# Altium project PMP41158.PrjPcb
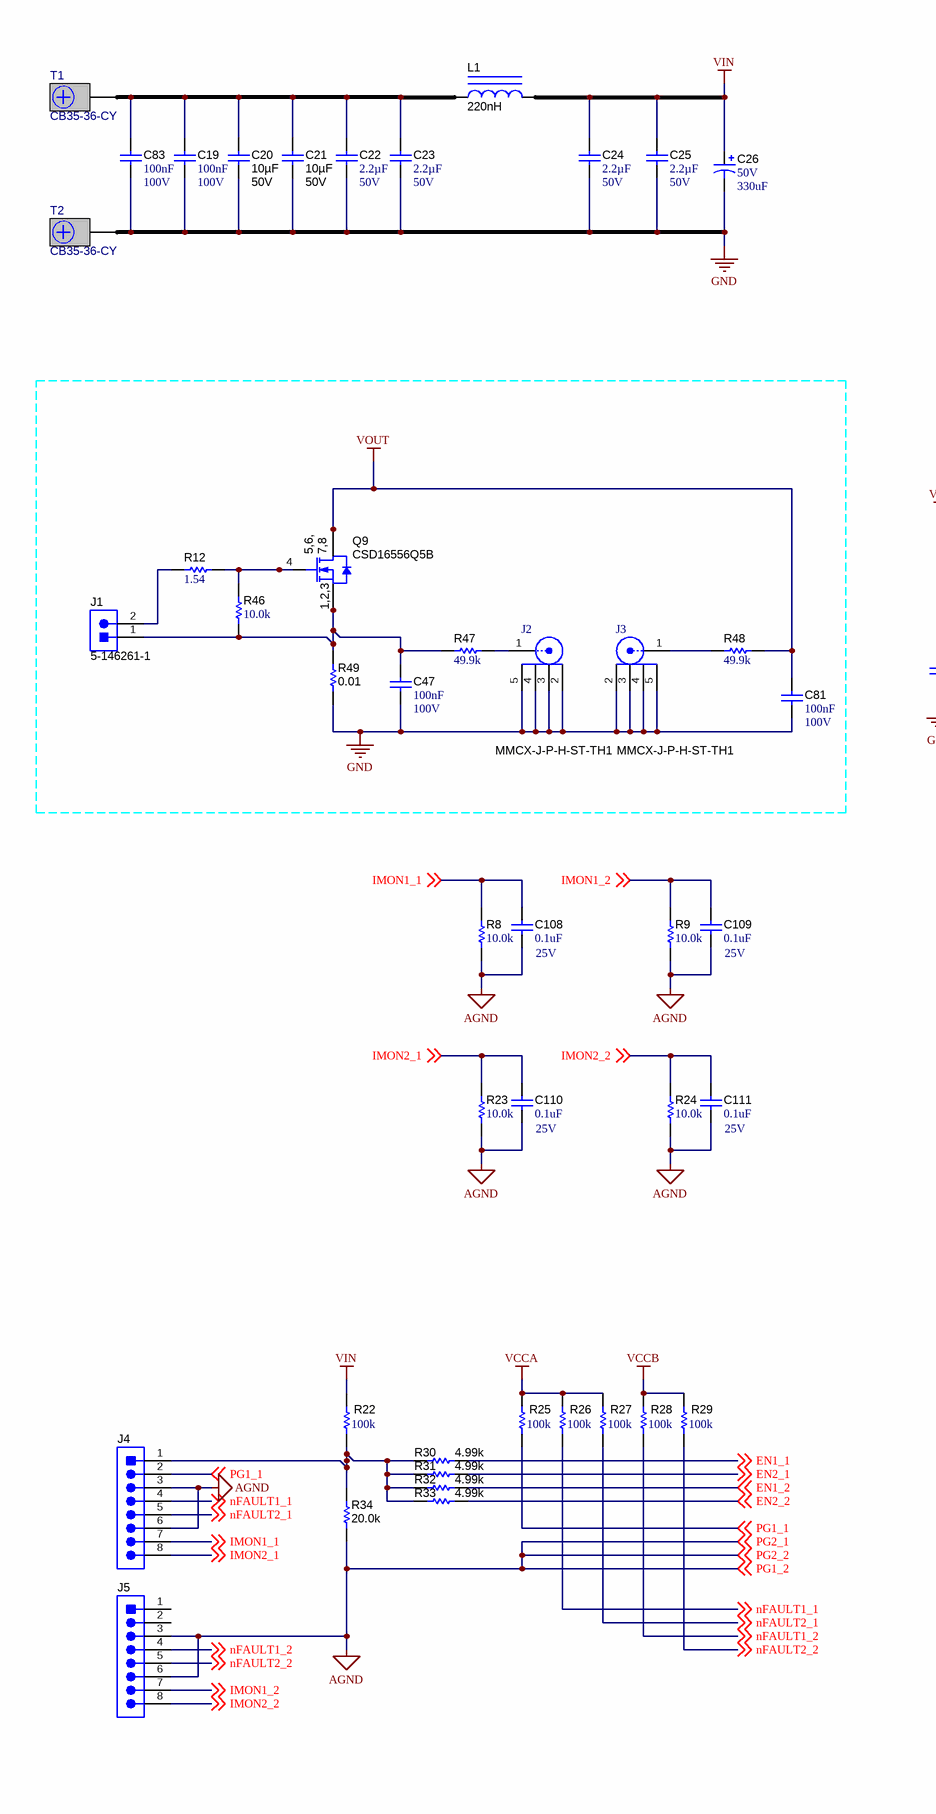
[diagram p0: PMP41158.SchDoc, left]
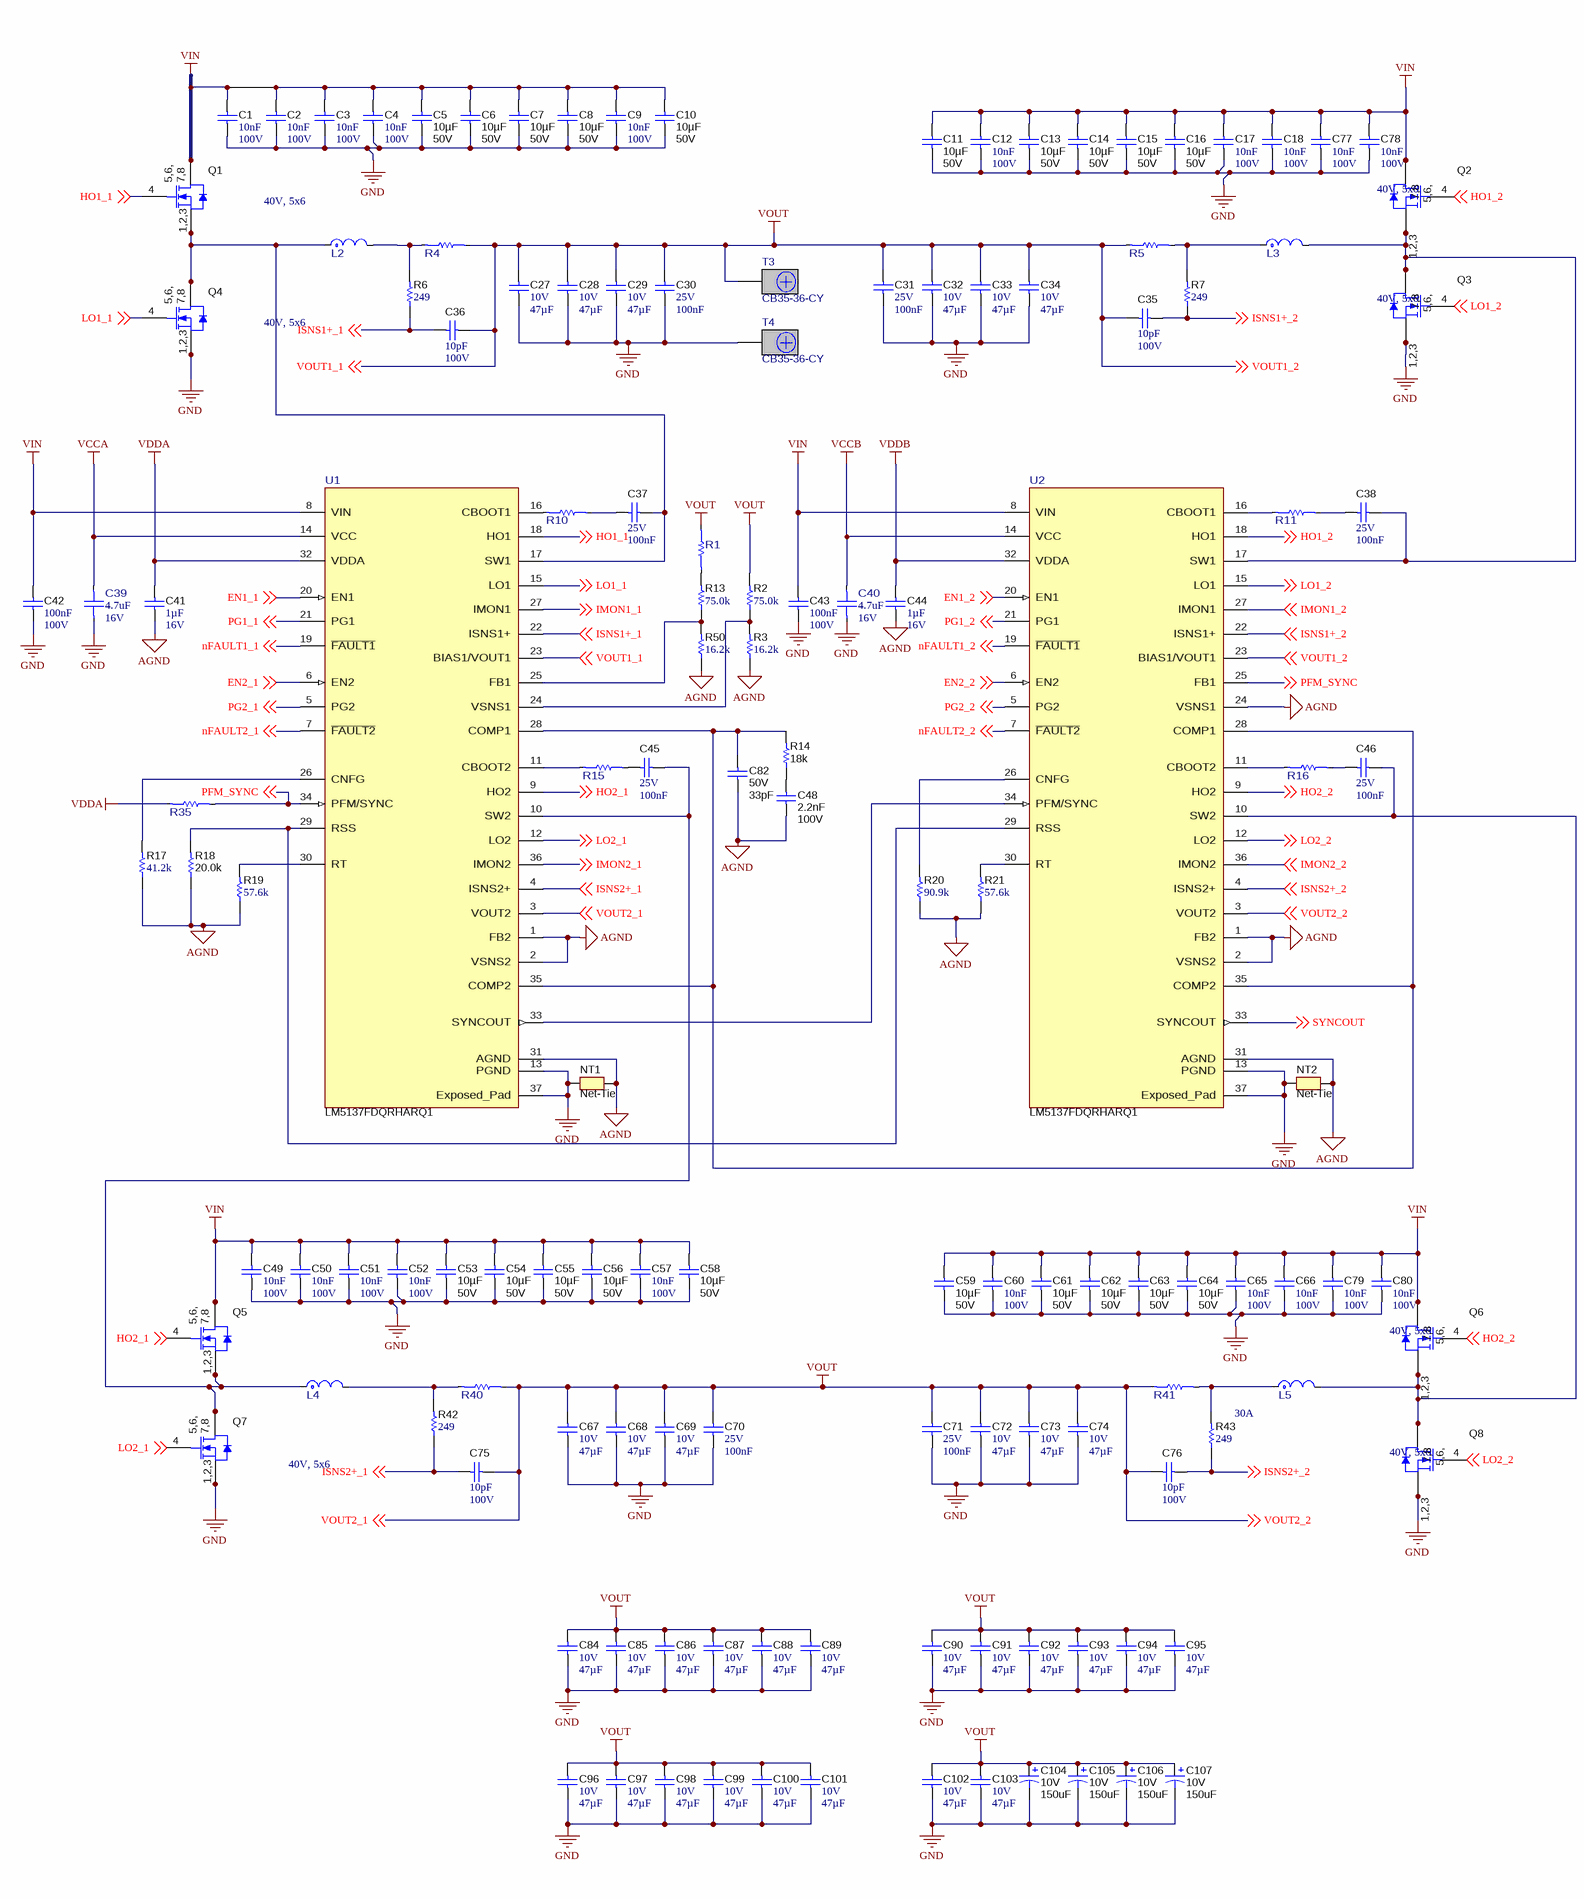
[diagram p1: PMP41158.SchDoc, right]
CopyrightYear: 2025; PCB_Layout: Shelly Xie; PCB_Rev: A; PRJ_Customer: Public Release; PRJ_Engineer: Shelly Xie; PRJ_Number: PMP41158; PRJ_Title: PMP41158; SCH_Rev: A; TechSupport: http://www.ti.com/support; TID: N/A
2 sheets, 203 parts. Net scope: global (net labels, ports and power ports of the same name join across sheets).
Board file: PMP41158-Finial.PcbDoc
Sheets:
  PMP41158.SchDoc
  PMP41158_Hardware.SchDoc

## Sheet PMP41158.SchDoc
size 558 x 431 mm; Date: Not shown in title block; ApprovedBy: Not shown in title block; CheckedBy: Not shown in title block; Author: Not shown in title block; CompanyName: Not shown in title block; Engineer: Not shown in title block; Organization: Not shown in title block; Address1: Not shown in title block; Address2: Not shown in title block; Address3: Not shown in title block; Address4: Not shown in title block; DocumentNumber: 2; Revision: Use project parameter SCH_Rev; SheetNumber: 1; SheetTotal: 2; PageSetup: Record=PageOptions¦CenterHorizontal=True¦CenterVertical=True¦PrintScale=1.00¦XCorrection=1.00¦YCorrection=1.00¦PrintKind=0¦BorderSize=5000000¦LeftOffset=0¦BottomOffset=0¦Orientation=2¦PaperLength=1000¦PaperWidth=1000¦Scale=100¦PaperSource=15¦PrintQuality=600¦MediaType=1¦DitherType=10¦PaperKind=Letter¦PrintScaleMode=1

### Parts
C1  Cap_F: 10nF  VDC_V: 100V  [0603]  (hidden comment: CGA3E2X7R2A103K080AA)
C2  Cap_F: 10nF  VDC_V: 100V  [0603]  (hidden comment: CGA3E2X7R2A103K080AA)
C3  Cap_F: 10nF  VDC_V: 100V  [0603]  (hidden comment: CGA3E2X7R2A103K080AA)
C4  Cap_F: 10nF  VDC_V: 100V  [0603]  (hidden comment: CGA3E2X7R2A103K080AA)
C5  ValueDisplayed: 10µF  VDC_V: 50V  [1210_280]  (hidden comment: CGA6P3X7S1H106K250AE)
C6  ValueDisplayed: 10µF  VDC_V: 50V  [1210_280]  (hidden comment: CGA6P3X7S1H106K250AE)
C7  ValueDisplayed: 10µF  VDC_V: 50V  [1210_280]  (hidden comment: CGA6P3X7S1H106K250AE)
C8  ValueDisplayed: 10µF  VDC_V: 50V  [1210_280]  (hidden comment: CGA6P3X7S1H106K250AE)
C9  Cap_F: 10nF  VDC_V: 100V  [0603]  (hidden comment: CGA3E2X7R2A103K080AA)
C10  ValueDisplayed: 10µF  VDC_V: 50V  [1210_280]  (hidden comment: CGA6P3X7S1H106K250AE)
C11  ValueDisplayed: 10µF  VDC_V: 50V  [1210_280]  (hidden comment: CGA6P3X7S1H106K250AE)
C12  Cap_F: 10nF  VDC_V: 100V  [0603]  (hidden comment: CGA3E2X7R2A103K080AA)
C13  ValueDisplayed: 10µF  VDC_V: 50V  [1210_280]  (hidden comment: CGA6P3X7S1H106K250AE)
C14  ValueDisplayed: 10µF  VDC_V: 50V  [1210_280]  (hidden comment: CGA6P3X7S1H106K250AE)
C15  ValueDisplayed: 10µF  VDC_V: 50V  [1210_280]  (hidden comment: CGA6P3X7S1H106K250AE)
C16  ValueDisplayed: 10µF  VDC_V: 50V  [1210_280]  (hidden comment: CGA6P3X7S1H106K250AE)
C17  Cap_F: 10nF  VDC_V: 100V  [0603]  (hidden comment: CGA3E2X7R2A103K080AA)
C18  Cap_F: 10nF  VDC_V: 100V  [0603]  (hidden comment: CGA3E2X7R2A103K080AA)
C19  Cap_F: 100nF  VDC_V: 100V  [0805_HV]  (hidden comment: GCM21BR72A104KA37L)
C20  ValueDisplayed: 10µF  VDC_V: 50V  [1210_280]  (hidden comment: CGA6P3X7S1H106K250AE)
C21  ValueDisplayed: 10µF  VDC_V: 50V  [1210_280]  (hidden comment: CGA6P3X7S1H106K250AE)
C22  Cap_F: 2.2µF  VDC_V: 50V  [0805L]  (hidden comment: CGA4J3X7R1H225K125AE)
C23  Cap_F: 2.2µF  VDC_V: 50V  [0805L]  (hidden comment: CGA4J3X7R1H225K125AE)
C24  Cap_F: 2.2µF  VDC_V: 50V  [0805L]  (hidden comment: CGA4J3X7R1H225K125AE)
C25  Cap_F: 2.2µF  VDC_V: 50V  [0805L]  (hidden comment: CGA4J3X7R1H225K125AE)
C26  VDC_V: 50V  ValueDisplayed: 330uF  [SM_RADIAL_H13]  (hidden comment: EEV-FK1H331Q)
C27  VDC_V: 10V  ValueDisplayed: 47µF  [1210_270]  (hidden comment: CGA6P1X7S1A476M250AC)
C28  VDC_V: 10V  ValueDisplayed: 47µF  [1210_270]  (hidden comment: CGA6P1X7S1A476M250AC)
C29  VDC_V: 10V  ValueDisplayed: 47µF  [1210_270]  (hidden comment: CGA6P1X7S1A476M250AC)
C30  VDC_V: 25V  Cap_F: 100nF  [0603]  (hidden comment: GCM188R71E104KA57D)
C31  VDC_V: 25V  Cap_F: 100nF  [0603]  (hidden comment: GCM188R71E104KA57D)
C32  VDC_V: 10V  ValueDisplayed: 47µF  [1210_270]  (hidden comment: CGA6P1X7S1A476M250AC)
C33  VDC_V: 10V  ValueDisplayed: 47µF  [1210_270]  (hidden comment: CGA6P1X7S1A476M250AC)
C34  VDC_V: 10V  ValueDisplayed: 47µF  [1210_270]  (hidden comment: CGA6P1X7S1A476M250AC)
C35  ValueDisplayed: 10pF  VDC_V: 100V  [0603L]  (hidden comment: GCM1885C2A100JA16D)
C36  ValueDisplayed: 10pF  VDC_V: 100V  [0603L]  (hidden comment: GCM1885C2A100JA16D)
C37  VDC_V: 25V  Cap_F: 100nF  [0603L]  (hidden comment: GCM188R71E104KA57D)
C38  VDC_V: 25V  Cap_F: 100nF  [0603L]  (hidden comment: GCM188R71E104KA57D)
C39  ValueDisplayed: 4.7uF  VDC_V: 16V  [FP-GRT188C71C475KE13D_0603-MFG]  (hidden comment: GRT188C71C475KE13D)
C40  ValueDisplayed: 4.7uF  VDC_V: 16V  [FP-GRT188C71C475KE13D_0603-MFG]  (hidden comment: GRT188C71C475KE13D)
C41  Cap_F: 1µF  VDC_V: 16V  [0603L]  (hidden comment: GCM188R71C105KA64J)
C42  Cap_F: 100nF  VDC_V: 100V  [0603L]  (hidden comment: HMK107B7104KAHT)
C43  Cap_F: 100nF  VDC_V: 100V  [0603L]  (hidden comment: HMK107B7104KAHT)
C44  Cap_F: 1µF  VDC_V: 16V  [0603L]  (hidden comment: GCM188R71C105KA64J)
C45  VDC_V: 25V  Cap_F: 100nF  [0603L]  (hidden comment: GCM188R71E104KA57D)
C46  VDC_V: 25V  Cap_F: 100nF  [0603L]  (hidden comment: GCM188R71E104KA57D)
C47  Cap_F: 100nF  VDC_V: 100V  [0603]  (hidden comment: HMK107B7104KAHT)
C48  Cap_F: 2.2nF  VDC_V: 100V  [0603L]  (hidden comment: CGA3E2X7R2A222K080AA)
C49  Cap_F: 10nF  VDC_V: 100V  [0603]  (hidden comment: CGA3E2X7R2A103K080AA)
C50  Cap_F: 10nF  VDC_V: 100V  [0603]  (hidden comment: CGA3E2X7R2A103K080AA)
C51  Cap_F: 10nF  VDC_V: 100V  [0603]  (hidden comment: CGA3E2X7R2A103K080AA)
C52  Cap_F: 10nF  VDC_V: 100V  [0603]  (hidden comment: CGA3E2X7R2A103K080AA)
C53  ValueDisplayed: 10µF  VDC_V: 50V  [1210_280]  (hidden comment: CGA6P3X7S1H106K250AE)
C54  ValueDisplayed: 10µF  VDC_V: 50V  [1210_280]  (hidden comment: CGA6P3X7S1H106K250AE)
C55  ValueDisplayed: 10µF  VDC_V: 50V  [1210_280]  (hidden comment: CGA6P3X7S1H106K250AE)
C56  ValueDisplayed: 10µF  VDC_V: 50V  [1210_280]  (hidden comment: CGA6P3X7S1H106K250AE)
C57  Cap_F: 10nF  VDC_V: 100V  [0603]  (hidden comment: CGA3E2X7R2A103K080AA)
C58  ValueDisplayed: 10µF  VDC_V: 50V  [1210_280]  (hidden comment: CGA6P3X7S1H106K250AE)
C59  ValueDisplayed: 10µF  VDC_V: 50V  [1210_280]  (hidden comment: CGA6P3X7S1H106K250AE)
C60  Cap_F: 10nF  VDC_V: 100V  [0603]  (hidden comment: CGA3E2X7R2A103K080AA)
C61  ValueDisplayed: 10µF  VDC_V: 50V  [1210_280]  (hidden comment: CGA6P3X7S1H106K250AE)
C62  ValueDisplayed: 10µF  VDC_V: 50V  [1210_280]  (hidden comment: CGA6P3X7S1H106K250AE)
C63  ValueDisplayed: 10µF  VDC_V: 50V  [1210_280]  (hidden comment: CGA6P3X7S1H106K250AE)
C64  ValueDisplayed: 10µF  VDC_V: 50V  [1210_280]  (hidden comment: CGA6P3X7S1H106K250AE)
C65  Cap_F: 10nF  VDC_V: 100V  [0603]  (hidden comment: CGA3E2X7R2A103K080AA)
C66  Cap_F: 10nF  VDC_V: 100V  [0603]  (hidden comment: CGA3E2X7R2A103K080AA)
C67  VDC_V: 10V  ValueDisplayed: 47µF  [1210_270]  (hidden comment: CGA6P1X7S1A476M250AC)
C68  VDC_V: 10V  ValueDisplayed: 47µF  [1210_270]  (hidden comment: CGA6P1X7S1A476M250AC)
C69  VDC_V: 10V  ValueDisplayed: 47µF  [1210_270]  (hidden comment: CGA6P1X7S1A476M250AC)
C70  VDC_V: 25V  Cap_F: 100nF  [0603]  (hidden comment: GCM188R71E104KA57D)
C71  VDC_V: 25V  Cap_F: 100nF  [0603]  (hidden comment: GCM188R71E104KA57D)
C72  VDC_V: 10V  ValueDisplayed: 47µF  [1210_270]  (hidden comment: CGA6P1X7S1A476M250AC)
C73  VDC_V: 10V  ValueDisplayed: 47µF  [1210_270]  (hidden comment: CGA6P1X7S1A476M250AC)
C74  VDC_V: 10V  ValueDisplayed: 47µF  [1210_270]  (hidden comment: CGA6P1X7S1A476M250AC)
C75  ValueDisplayed: 10pF  VDC_V: 100V  [0603L]  (hidden comment: GCM1885C2A100JA16D)
C76  ValueDisplayed: 10pF  VDC_V: 100V  [0603L]  (hidden comment: GCM1885C2A100JA16D)
C77  Cap_F: 10nF  VDC_V: 100V  [0603]  (hidden comment: CGA3E2X7R2A103K080AA)
C78  Cap_F: 10nF  VDC_V: 100V  [0603]  (hidden comment: CGA3E2X7R2A103K080AA)
C79  Cap_F: 10nF  VDC_V: 100V  [0603]  (hidden comment: CGA3E2X7R2A103K080AA)
C80  Cap_F: 10nF  VDC_V: 100V  [0603]  (hidden comment: CGA3E2X7R2A103K080AA)
C81  Cap_F: 100nF  VDC_V: 100V  [0603]  (hidden comment: HMK107B7104KAHT)
C82  VDC_V: 50V  ValueDisplayed: 33pF  [0603L]  (hidden comment: CGA3E2NP01H330J080AA)
C83  Cap_F: 100nF  VDC_V: 100V  [0805_HV]  (hidden comment: GCM21BR72A104KA37L)
C84  VDC_V: 10V  ValueDisplayed: 47µF  [1210_270]  (hidden comment: CGA6P1X7S1A476M250AC)
C85  VDC_V: 10V  ValueDisplayed: 47µF  [1210_270]  (hidden comment: CGA6P1X7S1A476M250AC)
C86  VDC_V: 10V  ValueDisplayed: 47µF  [1210_270]  (hidden comment: CGA6P1X7S1A476M250AC)
C87  VDC_V: 10V  ValueDisplayed: 47µF  [1210_270]  (hidden comment: CGA6P1X7S1A476M250AC)
C88  VDC_V: 10V  ValueDisplayed: 47µF  [1210_270]  (hidden comment: CGA6P1X7S1A476M250AC)
C89  VDC_V: 10V  ValueDisplayed: 47µF  [1210_270]  (hidden comment: CGA6P1X7S1A476M250AC)
C90  VDC_V: 10V  ValueDisplayed: 47µF  [1210_270]  (hidden comment: CGA6P1X7S1A476M250AC)
C91  VDC_V: 10V  ValueDisplayed: 47µF  [1210_270]  (hidden comment: CGA6P1X7S1A476M250AC)
C92  VDC_V: 10V  ValueDisplayed: 47µF  [1210_270]  (hidden comment: CGA6P1X7S1A476M250AC)
C93  VDC_V: 10V  ValueDisplayed: 47µF  [1210_270]  (hidden comment: CGA6P1X7S1A476M250AC)
C94  VDC_V: 10V  ValueDisplayed: 47µF  [1210_270]  (hidden comment: CGA6P1X7S1A476M250AC)
C95  VDC_V: 10V  ValueDisplayed: 47µF  [1210_270]  (hidden comment: CGA6P1X7S1A476M250AC)
C96  VDC_V: 10V  ValueDisplayed: 47µF  [1210_270]  (hidden comment: CGA6P1X7S1A476M250AC)
C97  VDC_V: 10V  ValueDisplayed: 47µF  [1210_270]  (hidden comment: CGA6P1X7S1A476M250AC)
C98  VDC_V: 10V  ValueDisplayed: 47µF  [1210_270]  (hidden comment: CGA6P1X7S1A476M250AC)
C99  VDC_V: 10V  ValueDisplayed: 47µF  [1210_270]  (hidden comment: CGA6P1X7S1A476M250AC)
C100  VDC_V: 10V  ValueDisplayed: 47µF  [1210_270]  (hidden comment: CGA6P1X7S1A476M250AC)
C101  VDC_V: 10V  ValueDisplayed: 47µF  [1210_270]  (hidden comment: CGA6P1X7S1A476M250AC)
C102  VDC_V: 10V  ValueDisplayed: 47µF  [1210_270]  (hidden comment: CGA6P1X7S1A476M250AC)
C103  VDC_V: 10V  ValueDisplayed: 47µF  [1210_270]  (hidden comment: CGA6P1X7S1A476M250AC)
C104  VDC_V: 10V  ValueDisplayed: 150uF  [SM_RADIAL_D]  (hidden comment: EEE-FK1A151P)
C105  VDC_V: 10V  ValueDisplayed: 150uF  [SM_RADIAL_D]  (hidden comment: EEE-FK1A151P)
C106  VDC_V: 10V  ValueDisplayed: 150uF  [SM_RADIAL_D]  (hidden comment: EEE-FK1A151P)
C107  VDC_V: 10V  ValueDisplayed: 150uF  [SM_RADIAL_D]  (hidden comment: EEE-FK1A151P)
C108  Value2: 25V  ValueDisplayed: 0.1uF  [0603L]  (hidden comment: CGA3E2X7R1E104K080AA)
C109  Value2: 25V  ValueDisplayed: 0.1uF  [0603L]  (hidden comment: CGA3E2X7R1E104K080AA)
C110  Value2: 25V  ValueDisplayed: 0.1uF  [0603L]  (hidden comment: CGA3E2X7R1E104K080AA)
C111  Value2: 25V  ValueDisplayed: 0.1uF  [0603L]  (hidden comment: CGA3E2X7R1E104K080AA)
J1  5-146261-1  [CONN_5-146261-1]
J2  MMCX-J-P-H-ST-TH1  [Samtec_MMCX-J-P-H-ST-TH1]
J3  MMCX-J-P-H-ST-TH1  [Samtec_MMCX-J-P-H-ST-TH1]
J4  TS-108-G-AA  [Samtec_TS-108-x-AA]  (value not drawn)
J5  TS-108-G-AA  [Samtec_TS-108-x-AA]  (value not drawn)
L1  ValueDisplayed: 220nH  [SRP1245A]  (hidden comment: SRP1245A-R22M)
L2  784373680015  [FP-VCHA105D-1R5MS6_SMT2_10MM85_10MM0-MFG]  (value not drawn)
L3  784373680015  [FP-VCHA105D-1R5MS6_SMT2_10MM85_10MM0-MFG]  (value not drawn)
L4  784373680015  [FP-VCHA105D-1R5MS6_SMT2_10MM85_10MM0-MFG]  (value not drawn)
L5  784373680015  [FP-VCHA105D-1R5MS6_SMT2_10MM85_10MM0-MFG]  (value not drawn)
NT1  Net-Tie  [Net-Tie_0805_HV_NoOverlay]  (net tie, no BOM)
NT2  Net-Tie  [Net-Tie_0805_HV_NoOverlay]  (net tie, no BOM)
Q1  IPC50N04S5L5R5ATMA1  [PG-TDSON-8-33]  (value not drawn)
Q2  IPC50N04S5L5R5ATMA1  [PG-TDSON-8-33]  (value not drawn)
Q3  IPC50N04S5L5R5ATMA1  [PG-TDSON-8-33]  (value not drawn)
Q4  IPC50N04S5L5R5ATMA1  [PG-TDSON-8-33]  (value not drawn)
Q5  IPC50N04S5L5R5ATMA1  [PG-TDSON-8-33]  (value not drawn)
Q6  IPC50N04S5L5R5ATMA1  [PG-TDSON-8-33]  (value not drawn)
Q7  IPC50N04S5L5R5ATMA1  [PG-TDSON-8-33]  (value not drawn)
Q8  IPC50N04S5L5R5ATMA1  [PG-TDSON-8-33]  (value not drawn)
Q9  CSD16556Q5B  [DNK0008A]
R1  RC0603FR-100RL  [FP-RC0603FR-100RL_0603-MFG]  (value not drawn)
R2  ValueDisplayed: 75.0k  [0603L]  (hidden comment: CRCW060375K0FKEA)
R3  ValueDisplayed: 16.2k  [0603L]  (hidden comment: CRCW060316K2FKEA)
R4  KRL6432E-M-R003-F-T1  [FP-KRL6432E-M-R003-F-T1_2512-MFG]  (value not drawn)
R5  KRL6432E-M-R003-F-T1  [FP-KRL6432E-M-R003-F-T1_2512-MFG]  (value not drawn)
R6  ValueDisplayed: 249  [0603L]  (hidden comment: CRCW0603249RFKEA)
R7  ValueDisplayed: 249  [0603L]  (hidden comment: CRCW0603249RFKEA)
R8  ValueDisplayed: 10.0k  [0603L]  (hidden comment: CRCW060310K0FKEA)
R9  ValueDisplayed: 10.0k  [0603L]  (hidden comment: CRCW060310K0FKEA)
R10  RC0603FR-100RL  [FP-RC0603FR-100RL_0603-MFG]  (value not drawn)
R11  RC0603FR-100RL  [FP-RC0603FR-100RL_0603-MFG]  (value not drawn)
R12  ValueDisplayed: 1.54  [0603]  (hidden comment: CRCW06031R54FKEA)
R13  ValueDisplayed: 75.0k  [0603L]  (hidden comment: CRCW060375K0FKEA)
R14  ValueDisplayed: 18k  [0603L]  (hidden comment: CRCW060318K0JNEA)
R15  RC0603FR-100RL  [FP-RC0603FR-100RL_0603-MFG]  (value not drawn)
R16  RC0603FR-100RL  [FP-RC0603FR-100RL_0603-MFG]  (value not drawn)
R17  ValueDisplayed: 41.2k  [0603L]  (hidden comment: CRCW060341K2FKEA)
R18  ValueDisplayed: 20.0k  [0603L]  (hidden comment: CRCW060320K0FKEA)
R19  ValueDisplayed: 57.6k  [0603L]  (hidden comment: CRCW060357K6FKEA)
R20  ValueDisplayed: 90.9k  [0603L]  (hidden comment: CRCW060390K9FKEA)
R21  ValueDisplayed: 57.6k  [0603L]  (hidden comment: CRCW060357K6FKEA)
R22  ValueDisplayed: 100k  [0603L]  (hidden comment: CRCW0603100KFKEA)
R23  ValueDisplayed: 10.0k  [0603L]  (hidden comment: CRCW060310K0FKEA)
R24  ValueDisplayed: 10.0k  [0603L]  (hidden comment: CRCW060310K0FKEA)
R25  ValueDisplayed: 100k  [0603L]  (hidden comment: CRCW0603100KFKEA)
R26  ValueDisplayed: 100k  [0603L]  (hidden comment: CRCW0603100KFKEA)
R27  ValueDisplayed: 100k  [0603L]  (hidden comment: CRCW0603100KFKEA)
R28  ValueDisplayed: 100k  [0603L]  (hidden comment: CRCW0603100KFKEA)
R29  ValueDisplayed: 100k  [0603L]  (hidden comment: CRCW0603100KFKEA)
R30  ValueDisplayed: 4.99k  [0603]  (hidden comment: CRCW06034K99FKEA)
R31  ValueDisplayed: 4.99k  [0603]  (hidden comment: CRCW06034K99FKEA)
R32  ValueDisplayed: 4.99k  [0603]  (hidden comment: CRCW06034K99FKEA)
R33  ValueDisplayed: 4.99k  [0603]  (hidden comment: CRCW06034K99FKEA)
R34  ValueDisplayed: 20.0k  [0603L]  (hidden comment: CRCW060320K0FKEA)
R35  RC0603FR-100RL  [FP-RC0603FR-100RL_0603-MFG]  (value not drawn)
R40  KRL6432E-M-R003-F-T1  [FP-KRL6432E-M-R003-F-T1_2512-MFG]  (value not drawn)
R41  KRL6432E-M-R003-F-T1  [FP-KRL6432E-M-R003-F-T1_2512-MFG]  (value not drawn)
R42  ValueDisplayed: 249  [0603L]  (hidden comment: CRCW0603249RFKEA)
R43  ValueDisplayed: 249  [0603L]  (hidden comment: CRCW0603249RFKEA)
R46  ValueDisplayed: 10.0k  [TNPW0603]  (hidden comment: TNPW060310K0BEEA)
R47  ValueDisplayed: 49.9k  [0603]  (hidden comment: CRCW060349K9FKEA)
R48  ValueDisplayed: 49.9k  [0603]  (hidden comment: CRCW060349K9FKEA)
R49  ValueDisplayed: 0.01  [2512]  (hidden comment: CRA2512-FZ-R010ELF)
R50  ValueDisplayed: 16.2k  [0603L]  (hidden comment: CRCW060316K2FKEA)
T1  CB35-36-CY  [CB35-36-CY]
T2  CB35-36-CY  [CB35-36-CY]
T3  CB35-36-CY  [CB35-36-CY]
T4  CB35-36-CY  [CB35-36-CY]
U1  LM5137FDQRHARQ1  [RHA0036D-MFG]
U2  LM5137FDQRHARQ1  [RHA0036D-MFG]

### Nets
AGND: C41.2 C44.2 C48.2 C82.2 C108.1 C109.1 C110.1 C111.1 J4.3 J4.6 J5.3 J5.6 NT1.2 NT2.2 R3.1 R8.2 R9.2 R17.1 R18.1 R19.1 R20.1 R21.1 R23.2 R24.2 R34.1 R50.1 U1.1(FB2) U1.2(VSNS2) U1.5(PG2) U1.31(AGND) U2.1(FB2) U2.2(VSNS2) U2.5(PG2) U2.21(PG1) U2.24(VSNS1) U2.31(AGND) ; off-sheet PG2_1, off-sheet PG1_2, off-sheet PG2_2  [also labelled PG1_2, PG2_1, PG2_2]
GND: C1.2 C2.2 C3.2 C4.2 C5.2 C6.2 C7.2 C8.2 C9.2 C10.2 C11.2 C12.2 C13.2 C14.2 C15.2 C16.2 C17.2 C18.2 C19.2 C20.2 C21.2 C22.2 C23.2 C24.2 C25.2 C26.2(-) C27.2 C28.2 C29.2 C30.2 C31.2 C32.2 C33.2 C34.2 C39.1 C40.1 C42.2 C43.2 C47.2 C49.2 C50.2 C51.2 C52.2 C53.2 C54.2 C55.2 C56.2 C57.2 C58.2 C59.2 C60.2 C61.2 C62.2 C63.2 C64.2 C65.2 C66.2 C67.2 C68.2 C69.2 C70.2 C71.2 C72.2 C73.2 C74.2 C77.2 C78.2 C79.2 C80.2 C81.2 C83.2 C84.2 C85.2 C86.2 C87.2 C88.2 C89.2 C90.2 C91.2 C92.2 C93.2 C94.2 C95.2 C96.2 C97.2 C98.2 C99.2 C100.2 C101.2 C102.2 C103.2 C104.2(-) C105.2(-) C106.2(-) C107.2(-) J2.2 J2.3 J2.4 J2.5 J3.2 J3.3 J3.4 J3.5 NT1.1 NT2.1 Q3.1(S) Q3.2(S) Q3.3(S) Q4.1(S) Q4.2(S) Q4.3(S) Q7.1(S) Q7.2(S) Q7.3(S) Q8.1(S) Q8.2(S) Q8.3(S) R49.1 T2.1 T4.1 U1.13(PGND) U1.37(Exposed_Pad) U2.13(PGND) U2.37(Exposed_Pad)
VCCA: C39.2 R25.2 R26.2 R27.2 U1.14(VCC)
VCCB: C40.2 R28.2 R29.2 U2.14(VCC)
VDDA: C41.1 R35.1 U1.32(VDDA)
VDDB: C44.1 U2.32(VDDA)
VIN: C1.1 C2.1 C3.1 C4.1 C5.1 C6.1 C7.1 C8.1 C9.1 C10.1 C11.1 C12.1 C13.1 C14.1 C15.1 C16.1 C17.1 C18.1 C24.1 C25.1 C26.1(+) C42.1 C43.1 C49.1 C50.1 C51.1 C52.1 C53.1 C54.1 C55.1 C56.1 C57.1 C58.1 C59.1 C60.1 C61.1 C62.1 C63.1 C64.1 C65.1 C66.1 C77.1 C78.1 C79.1 C80.1 L1.2 Q1.5(D) Q1.6(D) Q1.7(D) Q1.8(D) Q2.5(D) Q2.6(D) Q2.7(D) Q2.8(D) Q5.5(D) Q5.6(D) Q5.7(D) Q5.8(D) Q6.5(D) Q6.6(D) Q6.7(D) Q6.8(D) R22.2 U1.8(VIN) U2.8(VIN)
VOUT: C27.1 C28.1 C29.1 C30.1 C31.1 C32.1 C33.1 C34.1 C35.2 C36.1 C67.1 C68.1 C69.1 C70.1 C71.1 C72.1 C73.1 C74.1 C75.1 C76.2 C81.1 C84.1 C85.1 C86.1 C87.1 C88.1 C89.1 C90.1 C91.1 C92.1 C93.1 C94.1 C95.1 C96.1 C97.1 C98.1 C99.1 C100.1 C101.1 C102.1 C103.1 C104.1(+) C105.1(+) C106.1(+) C107.1(+) Q9.5(D) Q9.6(D) Q9.7(D) Q9.8(D) Q9.9(D) R1.2 R2.2 R4.2 R5.1 R40.2 R41.1 R48.2 T3.1 U1.3(VOUT2) U1.23(BIAS1/VOUT1) U2.3(VOUT2) U2.23(BIAS1/VOUT1) ; off-sheet VOUT1_1, off-sheet VOUT2_1, off-sheet VOUT1_2, off-sheet VOUT2_2  [also labelled VOUT1_1, VOUT1_2, VOUT2_1, VOUT2_2]
EN1_1: R30.2 U1.20(EN1) ; off-sheet EN1_1
EN1_2: R32.2 U2.20(EN1) ; off-sheet EN1_2
EN2_1: R31.2 U1.6(EN2) ; off-sheet EN2_1
EN2_2: R33.2 U2.6(EN2) ; off-sheet EN2_2
HO1_1: Q1.4(G) U1.18(HO1) ; off-sheet HO1_1
HO1_2: Q2.4(G) U2.18(HO1) ; off-sheet HO1_2
HO2_1: Q5.4(G) U1.9(HO2) ; off-sheet HO2_1
HO2_2: Q6.4(G) U2.9(HO2) ; off-sheet HO2_2
IMON1_1: C108.2 J4.7 R8.1 U1.27(IMON1) ; off-sheet IMON1_1
IMON1_2: C109.2 J5.7 R9.1 U2.27(IMON1) ; off-sheet IMON1_2
IMON2_1: C110.2 J4.8 R23.1 U1.36(IMON2) ; off-sheet IMON2_1
IMON2_2: C111.2 J5.8 R24.1 U2.36(IMON2) ; off-sheet IMON2_2
ISNS1+_1: C36.2 R6.1 U1.22(ISNS1+) ; off-sheet ISNS1+_1
ISNS1+_2: C35.1 R7.1 U2.22(ISNS1+) ; off-sheet ISNS1+_2
ISNS2+_1: C75.2 R42.1 U1.4(ISNS2+) ; off-sheet ISNS2+_1
ISNS2+_2: C76.1 R43.1 U2.4(ISNS2+) ; off-sheet ISNS2+_2
LO1_1: Q4.4(G) U1.15(LO1) ; off-sheet LO1_1
LO1_2: Q3.4(G) U2.15(LO1) ; off-sheet LO1_2
LO2_1: Q7.4(G) U1.12(LO2) ; off-sheet LO2_1
LO2_2: Q8.4(G) U2.12(LO2) ; off-sheet LO2_2
nFAULT1_1: J4.4 R26.1 U1.19(~{FAULT1}) ; off-sheet nFAULT1_1
nFAULT1_2: J5.4 R28.1 U2.19(~{FAULT1}) ; off-sheet nFAULT1_2
nFAULT2_1: J4.5 R27.1 U1.7(~{FAULT2}) ; off-sheet nFAULT2_1
nFAULT2_2: J5.5 R29.1 U2.7(~{FAULT2}) ; off-sheet nFAULT2_2
PFM_SYNC: R35.2 U1.34(PFM/SYNC) U2.25(FB1) ; off-sheet PFM_SYNC
PG1_1: J4.2 R25.1 U1.21(PG1) ; off-sheet PG1_1
SYNCOUT: U2.33(SYNCOUT) ; off-sheet SYNCOUT
NetC19_1: C19.1 C20.1 C21.1 C22.1 C23.1 C83.1 L1.1 T1.1
NetC37_1: C37.1 L2.1 Q1.1(S) Q1.2(S) Q1.3(S) Q4.5(D) Q4.6(D) Q4.7(D) Q4.8(D) U1.17(SW1)
NetC37_2: C37.2 R10.2
NetC38_1: C38.1 L3.2 Q2.1(S) Q2.2(S) Q2.3(S) Q3.5(D) Q3.6(D) Q3.7(D) Q3.8(D) U2.17(SW1)
NetC38_2: C38.2 R11.2
NetC45_1: C45.1 L4.1 Q5.1(S) Q5.2(S) Q5.3(S) Q7.5(D) Q7.6(D) Q7.7(D) Q7.8(D) U1.10(SW2)
NetC45_2: C45.2 R15.2
NetC46_1: C46.1 L5.2 Q6.1(S) Q6.2(S) Q6.3(S) Q8.5(D) Q8.6(D) Q8.7(D) Q8.8(D) U2.10(SW2)
NetC46_2: C46.2 R16.2
NetC47_1: C47.1 J1.1 Q9.1(S) Q9.2(S) Q9.3(S) R46.1 R47.1 R49.2
NetC48_1: C48.1 R14.1
NetC82_1: C82.1 R14.2 U1.28(COMP1) U1.35(COMP2) U2.28(COMP1) U2.35(COMP2)
NetJ1_2: J1.2 R12.1
NetJ2_1: J2.1 R47.2
NetJ3_1: J3.1 R48.1
NetJ4_1: J4.1 R22.1 R30.1 R31.1 R32.1 R33.1 R34.2
NetL2_2: L2.2 R4.1 R6.2
NetL3_1: L3.1 R5.2 R7.2
NetL4_2: L4.2 R40.1 R42.2
NetL5_1: L5.1 R41.2 R43.2
NetQ9_4: Q9.4(G) R12.2 R46.2
NetR1_1: R1.1 R13.2
NetR2_1: R2.1 R3.2 U1.24(VSNS1)
NetR10_1: R10.1 U1.16(CBOOT1)
NetR11_1: R11.1 U2.16(CBOOT1)
NetR13_1: R13.1 R50.2 U1.25(FB1)
NetR15_1: R15.1 U1.11(CBOOT2)
NetR16_1: R16.1 U2.11(CBOOT2)
NetR17_2: R17.2 U1.26(CNFG)
NetR18_2: R18.2 U1.29(RSS) U2.29(RSS)
NetR19_2: R19.2 U1.30(RT)
NetR20_2: R20.2 U2.26(CNFG)
NetR21_2: R21.2 U2.30(RT)
NetU1_33: U1.33(SYNCOUT) U2.34(PFM/SYNC)

Not connected (* = marked no-connect by the designer): J5 1 2

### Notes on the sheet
- (near Q1) 40V, 5x6
- 40V, 5x6
- (near Q3) 40V, 5x6
- (near Q4) 40V, 5x6
- 30A
- (near Q8) 40V, 5x6
- (near Q7) 40V, 5x6

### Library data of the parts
C1-C4 C9 C12 C17 C18 C49-C52 C57 C60 C65 C66 C77-C80 = CMP-0007082-1: CAP, CERM, 0.01 uF, 100 V, +/- 10%, X7R, AEC-Q200 Grade 1, 0603; Manufacturer: TDK; TaMin_C: -55°C; ESR_ohm: 0.2354; Polarized: N; SizeAreaWB_mm2: 4.68; Value1: 0.235428 ohm; U/M: EA; Value: 0.01uF; TaMax_C: 125°C; SizeZ_mm: 1; SizeX_mm: 1.6; SizeY_mm: 0.8; SizeArea_mm2: 1.28; AEC Qualified: Y; IRMS_A: 396.995mA; AEC Category: Q200
C5-C8 C10 C11 C13-C16 C20 C21 C53-C56 C58 C59 C61-C64 = CMP-0085350-1: CAP, CERM, 10 µF, 50 V,+/- 10%, X7S, AEC-Q200 Grade 1, 1210; Manufacturer: TDK; SizeZ_mm: 2.8; SizeY_mm: 2.5; SizeAreaWB_mm2: 14.7; AEC Qualified: Y; SizeArea_mm2: 8; U/M: EA; Value: 10uF; Polarized: N; TaMax_C: 125°C; SizeX_mm: 3.2; Cap_Case: 1210; TaMin_C: -55°C; AEC Grade: 1; AEC Category: Q200
C19 C83 = CMP-0860440-1: CAP, CERM, 0.1 µF, 100 V,+/- 10%, X7R, AEC-Q200 Grade 1, 0805; Manufacturer: MuRata; SizeY_mm: 1.25; ValueDisplayed: 0.1µF; SizeX_mm: 2; Cap_Case: 0805; AEC Grade: 1; Polarized: N; Value: 0.1uF; TaMin_C: -55°C; SizeZ_mm: 1.45; TaMax_C: 125°C; U/M: EA; SizeArea_mm2: 2.5; AEC Qualified: Y; SizeAreaWB_mm2: 6.75; AEC Category: Q200
C22-C25 = CMP-0860897-1: CAP, CERM, 2.2 µF, 50 V,+/- 10%, X7R, AEC-Q200 Grade 1, 0805; Manufacturer: TDK; SizeAreaWB_mm2: 6.75; U/M: EA; TaMin_C: -55°C; Cap_Case: 0805; Value: 2.2uF; AEC Category: Q200; SizeArea_mm2: 2.5; SizeY_mm: 1.25; Polarized: N; AEC Grade: 1; SizeZ_mm: 1.45; AEC Qualified: Y; TaMax_C: 125°C; SizeX_mm: 2
C26 = CMP-0011211-2: CAP, AL, 330 uF, 50 V, +/- 20%, 0.12 ohm, AEC-Q200 Grade 2, SMD; Manufacturer: Panasonic; TaMin_C: -55°C; ESR_ohm: 0.12; Polarized: Y; SizeAreaWB_mm2: 263.5; U/M: EA; Value: 330uF; TaMax_C: 105°C; SizeZ_mm: 13.5; SizeX_mm: 15; Cap_Case: H13; SizeArea_mm2: 202.5; CompType: Capacitor; Cap_F: 330µF; IRMS_A: 900mA; AEC Grade: 2; AEC Category: Q200
C27-C29 C32-C34 C67-C69 C72-C74 C84-C103 = CMP-0079933-1: CAP, CERM, 47 µF, 10 V,+/- 10%, X7S, AEC-Q200 Grade 1, 1210; Manufacturer: TDK; SizeAreaWB_mm2: 14.7; SizeArea_mm2: 8; AEC Qualified: Y; AEC Category: Q200; Value: 47uF; TaMax_C: 125°C; SizeZ_mm: 2.7; AEC Grade: 1; Polarized: N; TaMin_C: -55°C; SizeY_mm: 2.5; U/M: EA; SizeX_mm: 3.2; Cap_Case: 1210
C30 C31 C70 C71 = CMP-0084679-1: CAP, CERM, 0.1 µF, 25 V,+/- 10%, X7R, AEC-Q200 Grade 1, 0603; Manufacturer: MuRata; TaMin_C: -55°C; SizeY_mm: 0.8; Polarized: N; SizeArea_mm2: 1.28; SizeZ_mm: 1; SizeX_mm: 1.6; AEC Qualified: Y; AEC Category: Q200; Value: 0.1uF; ValueDisplayed: 0.1µF; TaMax_C: 125°C; U/M: EA; SizeAreaWB_mm2: 4.68
C35 C36 C75 C76 = CMP-0084283-1: CAP, CERM, 10 pF, 100 V,+/- 5%, C0G/NP0, AEC-Q200 Grade 1, 0603; Manufacturer: MuRata; TaMax_C: 125°C; Cap_Case: 0603; SizeX_mm: 1.6; SizeY_mm: 0.8; SizeArea_mm2: 1.28; Polarized: N; AEC Category: Q200; SizeAreaWB_mm2: 4.68; AEC Qualified: Y; SizeZ_mm: 1; Value: 10pF; U/M: EA; TaMin_C: -55°C
C37 C38 C45 C46 = CMP-0084679-1: CAP, CERM, 0.1 µF, 25 V,+/- 10%, X7R, AEC-Q200 Grade 1, 0603; Manufacturer: MuRata; TaMin_C: -55°C; SizeY_mm: 0.8; Polarized: N; SizeArea_mm2: 1.28; Cap_Case: 0603; SizeZ_mm: 1; SizeX_mm: 1.6; AEC Qualified: Y; AEC Category: Q200; Value: 0.1uF; ValueDisplayed: 0.1µF; TaMax_C: 125°C; U/M: EA; SizeAreaWB_mm2: 4.68
C39 C40 = CMP-0098105-1: AEC-Q200 Compliant Chip Multilayer Ceramic Capacitor for Infotainment 4.7uF ±10% 16V X7S SMD 0603; Manufacturer: Murata; Cap_F: 4.7µF; Value: 4.7µF; TempCo: 22%; SizeZ_mm: 1mm; AEC Grade: Grade 1; AEC Qualified: Yes
C41 C44 = CMP-0079154-1: CAP, CERM, 1 µF, 16 V,+/- 10%, X7R, AEC-Q200 Grade 1, 0603; Manufacturer: MuRata; SizeAreaWB_mm2: 4.68; SizeArea_mm2: 1.28; AEC Qualified: Y; AEC Category: Q200; Value: 1uF; TaMax_C: 125°C; SizeZ_mm: 1; Polarized: N; TaMin_C: -55°C; SizeY_mm: 0.8; U/M: EA; SizeX_mm: 1.6; Cap_Case: 0603
C42 C43 = CMP-0081011-1: CAP, CERM, 0.1 µF, 100 V,+/- 10%, X7R, AEC-Q200 Grade 1, 0603; Manufacturer: Taiyo Yuden; SizeAreaWB_mm2: 4.68; SizeArea_mm2: 1.28; AEC Qualified: Y; AEC Category: Q200; Value: 0.1uF; TaMax_C: 125°C; SizeZ_mm: 1; Polarized: N; TaMin_C: -55°C; SizeY_mm: 0.8; U/M: EA; SizeX_mm: 1.6; Cap_Case: 0603; ValueDisplayed: 0.1µF
C47 C81 = CMP-0081011-1: CAP, CERM, 0.1 µF, 100 V,+/- 10%, X7R, AEC-Q200 Grade 1, 0603; Manufacturer: Taiyo Yuden; SizeAreaWB_mm2: 4.68; SizeArea_mm2: 1.28; AEC Qualified: Y; AEC Category: Q200; Value: 0.1uF; TaMax_C: 125°C; SizeZ_mm: 1; Polarized: N; TaMin_C: -55°C; SizeY_mm: 0.8; U/M: EA; SizeX_mm: 1.6; ValueDisplayed: 0.1µF
C48 = CMP-0007085-1: CAP, CERM, 2200 pF, 100 V, +/- 10%, X7R, AEC-Q200 Grade 1, 0603; Manufacturer: TDK; TaMin_C: -55°C; ESR_ohm: 0.9239; Polarized: N; SizeAreaWB_mm2: 4.68; Value1: 0.923948 ohm; U/M: EA; Value: 2200pF; TaMax_C: 125°C; SizeZ_mm: 1; SizeX_mm: 1.6; SizeY_mm: 0.8; Cap_Case: 0603; SizeArea_mm2: 1.28; AEC Qualified: Y; IRMS_A: 295.638mA; AEC Category: Q200
C82 = CMP-0007076-2: CAP, CERM, 33 pF, 50 V, +/- 5%, C0G/NP0, AEC-Q200 Grade 0, 0603; Manufacturer: TDK; TaMin_C: -55°C; Polarized: N; SizeAreaWB_mm2: 4.68; Value1: Unknown; U/M: EA; Value: 33pF; TaMax_C: 150°C; SizeZ_mm: 1; SizeX_mm: 1.6; SizeY_mm: 0.8; Cap_Case: 0603; SizeArea_mm2: 1.28; AEC Qualified: Y; AEC Grade: 0; AEC Category: Q200
C104-C107 = CMP-0010687-1: CAP, AL, 150 uF, 10 V, +/- 20%, 0.36 ohm, AEC-Q200 Grade 2, SMD; Manufacturer: Panasonic; TaMin_C: -55°C; ESR_ohm: 0.36; Polarized: Y; SizeAreaWB_mm2: 84.28; U/M: EA; Value: 150uF; TaMax_C: 105°C; SizeZ_mm: 5.4; SizeX_mm: 7.8; SizeY_mm: 6.6; Cap_Case: D; SizeArea_mm2: 51.48; CompType: Capacitor; Cap_F: 150µF; IRMS_A: 240mA; AEC Grade: 2; AEC Category: Q200
C108-C111 = CMP-0007077-5: CAP, CERM, 0.1 uF, 25 V, +/- 10%, X7R, AEC-Q200 Grade 1, 0603; Manufacturer: TDK; TaMin_C: -55°C; Polarized: N; SizeAreaWB_mm2: 4.68; Value1: Unknown; U/M: EA; Value: 0.1uF; TaMax_C: 125°C; SizeZ_mm: 1; SizeX_mm: 1.6; SizeY_mm: 0.8; Cap_Case: 0603; SizeArea_mm2: 1.28; AEC Qualified: Y; Cap_F: 100nF; AEC Category: Q200
J1 = CMP-0054947-1: Header, 100mil, 2x1, Gold, TH; Manufacturer: TE Connectivity; CT: FALSE; Green_REACh: Passed; CNHeader: TRUE; Green_Lifecycle: Active
J2 J3 = CMP-0075554-1: Connector, MMCX 50 ohm, TH; Manufacturer: Samtec; CT: False; Gender: Female
J4 J5 = CMP-0084415-1: Header, 2.54mm, 8x1, Gold, TH; Manufacturer: Samtec; Row_Count: 1; Cert_UL: Y; Pitch_mm: 2.54; Gender: Male; Shrouded: N
L1 = CMP-0056879-1: Inductor, Wirewound, 220 nH, 52 A, 0.0005 ohm, AEC-Q200 Grade 0, SMD; Manufacturer: Bourns; Isat: 110A @ 20% inductance drop; Irms: 52A @ 40C rise; Green_Lifecycle: Active; SizeAreaWB_mm2: 224.75; DCR_ohm: 500µ; Green_REACh: Passed; Value: 220nH; Imax_A: 52A; SizeZ_mm: 5; SizeX_mm: 13.5; SizeY_mm: 12.5; SizeArea_mm2: 168.75; AEC Qualified: Y; AEC Grade: 0; AEC Category: Q200
L2-L5 = CMP-0095579-1: Power Choke Coil  type 1.5uH 20% 4.2mOhm 24.8A; PartNumber: '784373680015; Manufacturer: WURTH; Ind_H: 1.5µH; AEC Grade: Grade 0; DCR_ohm: 4.2m; Material: Metal Dust; Test Frequency: 100kHz; Isat: 26.8A; Standoff Height: 0mm; AEC Qualified: Yes; SizeZ_mm: 5.4mm
NT1 NT2 = CMP-0078142-4: Single point connection between nets.
Q1-Q8 = CMP-0080659-3: MOSFET, N-CH, 40 V, 50 A, AEC-Q101, SON-8; Manufacturer: Infineon Technologies; Alternate Manufacturer: None; Value1: 0.0079 ohm; IdsMax_A: 50A; SizeZ_mm: 1.1; QgTyp_nC: 17; SizeX_mm: 6.44; AEC Category: Q101; Rdson45_ohm: 7.9m; VdsMax_V: 40V; Value: 40V; Value2: 17 nC; SizeAreaWB_mm2: 60.35; ChMode: Enhancement; SizeArea_mm2: 33.17; SizeY_mm: 5.15; Vgs_V: 16V; ChType: N; AEC Qualified: Y
Q9 = CMP-0000273-2: MOSFET, N-CH, 25 V, 40 A, DNK0008A (VSON-CLIP-8); Alternate Manufacturer: None; Manufacturer: Texas Instruments; SizeZ_mm: 1; ChType: N; Value2: 36 nC; Value1: 0.001; VdsMax_V: 25V; SizeX_mm: 6; SizeY_mm: 5; Vgs_V: 20V; Value: 25V; Rdson45_ohm: 1.2m; SizeArea_mm2: 30; AEC Category: Q101; IdsMax_A: 40A; SizeAreaWB_mm2: 56; U/M: EA; QgTyp_nC: 36
R1 R10 R11 R15 R16 R35 = CMP-0123755-1: 0 Ohms Jumper Chip Resistor 0603 (1608 Metric) Moisture Resistant Thick Film; Manufacturer: Yageo; AEC Qualified: No; Res_ohm: 0; SizeZ_mm: 0.55mm; Tolerance_%: 1%; Value: 0
R2 R13 = CMP-0022589-4: RES, 75.0 k, 1%, 0.1 W, AEC-Q200 Grade 0, 0603; Manufacturer: Vishay-Dale; Power_W: 100mW; TempCo: 100 ppm/C; Value_Code: 75k0; Value: 75.0k; EIA_Code: E96; Res_ohm: 75k; SizeX_mm: 1.6; SizeY_mm: 0.8; SizeZ_mm: 1; Value2: 0.1W; SizeArea_mm2: 1.28; AEC Qualified: Y; VDC_V: 75V; AEC Category: Q200; AEC Grade: 0
R3 R50 = CMP-0022079-4: RES, 16.2 k, 1%, 0.1 W, AEC-Q200 Grade 0, 0603; Manufacturer: Vishay-Dale; Power_W: 100mW; TempCo: 100 ppm/C; Value_Code: 16k2; Value: 16.2k; EIA_Code: E96; SizeX_mm: 1.6; SizeY_mm: 0.8; SizeZ_mm: 1; Value2: 0.1W; SizeArea_mm2: 1.28; AEC Qualified: Y; VDC_V: 75V; AEC Category: Q200; AEC Grade: 0
R4 R5 R40 R41 = CMP-0122627-1: 3 mOhms ±1% 3W Chip Resistor Wide 2512 (6432 Metric), 1225 Automotive AEC-Q200, Current Sense Metal Foil; Manufacturer: Susumu; AEC Grade: Grade 0; AEC Qualified: Yes; Res_ohm: 3m; SizeZ_mm: 0.7mm; TempCo: 50ppm/°C; Value: 3m
R6 R7 R42 R43 = CMP-0022235-5: RES, 249, 1%, 0.1 W, AEC-Q200 Grade 0, 0603; Manufacturer: Vishay-Dale; Power_W: 100mW; TempCo: 100 ppm/C; Value_Code: 249R; Value: 249; EIA_Code: E96; SizeX_mm: 1.6; SizeY_mm: 0.8; SizeZ_mm: 1; Value2: 0.1W; SizeArea_mm2: 1.28; AEC Qualified: Y; VDC_V: 75V; AEC Category: Q200; AEC Grade: 0
R8 R9 R23 R24 = CMP-0021998-4: RES, 10.0 k, 1%, 0.1 W, AEC-Q200 Grade 0, 0603; Manufacturer: Vishay-Dale; Power_W: 100mW; TempCo: 100 ppm/C; Value_Code: 10k0; Value: 10.0k; EIA_Code: E96; Res_ohm: 10k; SizeX_mm: 1.6; SizeY_mm: 0.8; SizeZ_mm: 1; Value2: 0.1W; SizeArea_mm2: 1.28; AEC Qualified: Y; VDC_V: 75V; AEC Category: Q200; AEC Grade: 0
R12 = CMP-0022188-4: RES, 1.54, 1%, 0.1 W, AEC-Q200 Grade 0, 0603; Manufacturer: Vishay-Dale; Power_W: 100mW; TempCo: 100 ppm/C; Value_Code: 1R54; Value: 1.54; EIA_Code: E96; SizeX_mm: 1.6; SizeY_mm: 0.8; SizeZ_mm: 1; Value2: 0.1W; SizeArea_mm2: 1.28; AEC Qualified: Y; VDC_V: 75V; AEC Category: Q200; AEC Grade: 0
R14 = CMP-0025727-4: RES, 18 k, 5%, 0.1 W, AEC-Q200 Grade 0, 0603; Manufacturer: Vishay-Dale; Power_W: 100mW; TempCo: 200 ppm/C; Value_Code: 18k0; Value: 18k; EIA_Code: E24; SizeX_mm: 1.6; SizeY_mm: 0.8; SizeZ_mm: 1; Value2: 0.1W; SizeArea_mm2: 1.28; AEC Qualified: Y; VDC_V: 75V; AEC Category: Q200; AEC Grade: 0
R17 = CMP-0022414-4: RES, 41.2 k, 1%, 0.1 W, AEC-Q200 Grade 0, 0603; Manufacturer: Vishay-Dale; Power_W: 100mW; TempCo: 100 ppm/C; Value_Code: 41k2; Value: 41.2k; EIA_Code: E96; SizeX_mm: 1.6; SizeY_mm: 0.8; SizeZ_mm: 1; Value2: 0.1W; SizeArea_mm2: 1.28; AEC Qualified: Y; VDC_V: 75V; AEC Category: Q200; AEC Grade: 0
R18 R34 = CMP-0022204-4: RES, 20.0 k, 1%, 0.1 W, AEC-Q200 Grade 0, 0603; Manufacturer: Vishay-Dale; Power_W: 100mW; TempCo: 100 ppm/C; Value_Code: 20k0; Value: 20.0k; EIA_Code: E96; Res_ohm: 20k; SizeX_mm: 1.6; SizeY_mm: 0.8; SizeZ_mm: 1; Value2: 0.1W; SizeArea_mm2: 1.28; AEC Qualified: Y; VDC_V: 75V; AEC Category: Q200; AEC Grade: 0
R19 R21 = CMP-0022503-4: RES, 57.6 k, 1%, 0.1 W, AEC-Q200 Grade 0, 0603; Manufacturer: Vishay-Dale; Power_W: 100mW; TempCo: 100 ppm/C; Value_Code: 57k6; Value: 57.6k; EIA_Code: E96; SizeX_mm: 1.6; SizeY_mm: 0.8; SizeZ_mm: 1; Value2: 0.1W; SizeArea_mm2: 1.28; AEC Qualified: Y; VDC_V: 75V; AEC Category: Q200; AEC Grade: 0
R20 = CMP-0022651-4: RES, 90.9 k, 1%, 0.1 W, AEC-Q200 Grade 0, 0603; Manufacturer: Vishay-Dale; Power_W: 100mW; TempCo: 100 ppm/C; Value_Code: 90k9; Value: 90.9k; EIA_Code: E96; SizeY_mm: 0.8; SizeZ_mm: 1; Value2: 0.1W; SizeArea_mm2: 1.28; SizeX_mm: 1.6; AEC Qualified: Y; VDC_V: 75V; AEC Category: Q200; AEC Grade: 0
R22 R25-R29 = CMP-0021990-4: RES, 100 k, 1%, 0.1 W, AEC-Q200 Grade 0, 0603; Manufacturer: Vishay-Dale; Power_W: 100mW; TempCo: 100 ppm/C; Value: 100k; EIA_Code: E96; SizeX_mm: 1.6; SizeY_mm: 0.8; SizeZ_mm: 1; Value2: 0.1W; SizeArea_mm2: 1.28; AEC Qualified: Y; VDC_V: 75V; AEC Category: Q200; AEC Grade: 0
R30-R33 = CMP-0022458-4: RES, 4.99 k, 1%, 0.1 W, AEC-Q200 Grade 0, 0603; Manufacturer: Vishay-Dale; Power_W: 100mW; TempCo: 100 ppm/C; Value_Code: 4k99; Value: 4.99k; EIA_Code: E96; SizeX_mm: 1.6; SizeY_mm: 0.8; SizeZ_mm: 1; Value2: 0.1W; SizeArea_mm2: 1.28; AEC Qualified: Y; VDC_V: 75V; AEC Category: Q200; AEC Grade: 0
R46 = CMP-0025686-1: RES, 10.0 k, 0.1%, 0.1 W, AEC-Q200 Grade 1, 0603; Manufacturer: Vishay-Dale; Power_W: 100mW; TempCo: 25 ppm/C; Value_Code: 10k0; U/M: EA; Value: 10.0k; EIA_Code: E192; Res_ohm: 10k; SizeX_mm: 1.6; SizeY_mm: 0.85; SizeZ_mm: 0.55; Value2: 0.1W; SizeArea_mm2: 1.36; AEC Qualified: Y; VDC_V: 75V; AEC Grade: 1; AEC Category: Q200
R47 R48 = CMP-0022447-4: RES, 49.9 k, 1%, 0.1 W, AEC-Q200 Grade 0, 0603; Manufacturer: Vishay-Dale; Power_W: 100mW; TempCo: 100 ppm/C; Value_Code: 49k9; Value: 49.9k; EIA_Code: E96; SizeX_mm: 1.6; SizeY_mm: 0.8; SizeZ_mm: 1; Value2: 0.1W; SizeArea_mm2: 1.28; AEC Qualified: Y; VDC_V: 75V; AEC Category: Q200; AEC Grade: 0
R49 = CMP-0015418-2: RES, 0.01, 1%, 3 W, 2512; Manufacturer: Bourns; Power_W: 3W; TempCo: 75 ppm/C; Value_Code: R010; U/M: EA; Value: 0.01; EIA_Code: E96; Res_ohm: 10m; SizeX_mm: 6.3; SizeY_mm: 3.2; SizeZ_mm: 0.71; SizeArea_mm2: 20.16; AEC Category: Q200
T1-T4 = CMP-0055442-1: Terminal 50A Lug; Manufacturer: Panduit; CNHeader: FALSE; Green_Lifecycle: Not Set; Cert_CULUS: Y; Green_REACh: Incomplete; Voltage_V: 600V; CompType: Screw Terminal; ContactFinish: Copper
U1 U2 = CMP-0122321-1: Automotive, 4-V to 80-V, Functional Safety-Compliant, Dual Synchronous Buck Controller With Low IQ; Manufacturer: Texas Instruments; SizeZ_mm: 1mm; AEC Qualified: Yes; AEC Grade: Grade 1; Max Duty Cycle: 100%; Max Supply Voltage: 80V; Min Supply Voltage: 4V; Nominal Supply Current: 130uA; Number Of Outputs: 2; Output Type: AdjustableProgrammable; Output Voltage: 0.8-60V; Standoff Height: 0mm; Switching Frequency: 100-2200kHz; TaMax_C: +150°C; TaMin_C: -40°C

## Sheet PMP41158_Hardware.SchDoc
size 431 x 279 mm; Date: Not shown in title block; ApprovedBy: Not shown in title block; CheckedBy: Not shown in title block; Author: Not shown in title block; CompanyName: Not shown in title block; Engineer: Not shown in title block; Organization: Not shown in title block; Address1: Not shown in title block; Address2: Not shown in title block; Address3: Not shown in title block; Address4: Not shown in title block; DocumentNumber: 3; Revision: Use project parameter SCH_Rev; SheetNumber: 1; SheetTotal: 2; PageSetup: Record=PageOptions¦CenterHorizontal=True¦CenterVertical=True¦PrintScale=1.00¦XCorrection=1.00¦YCorrection=1.00¦PrintKind=0¦BorderSize=5000000¦LeftOffset=0¦BottomOffset=0¦Orientation=2¦PaperLength=1000¦PaperWidth=1000¦Scale=100¦PaperSource=15¦PrintQuality=600¦MediaType=1¦DitherType=10¦PaperKind=Letter¦PrintScaleMode=1
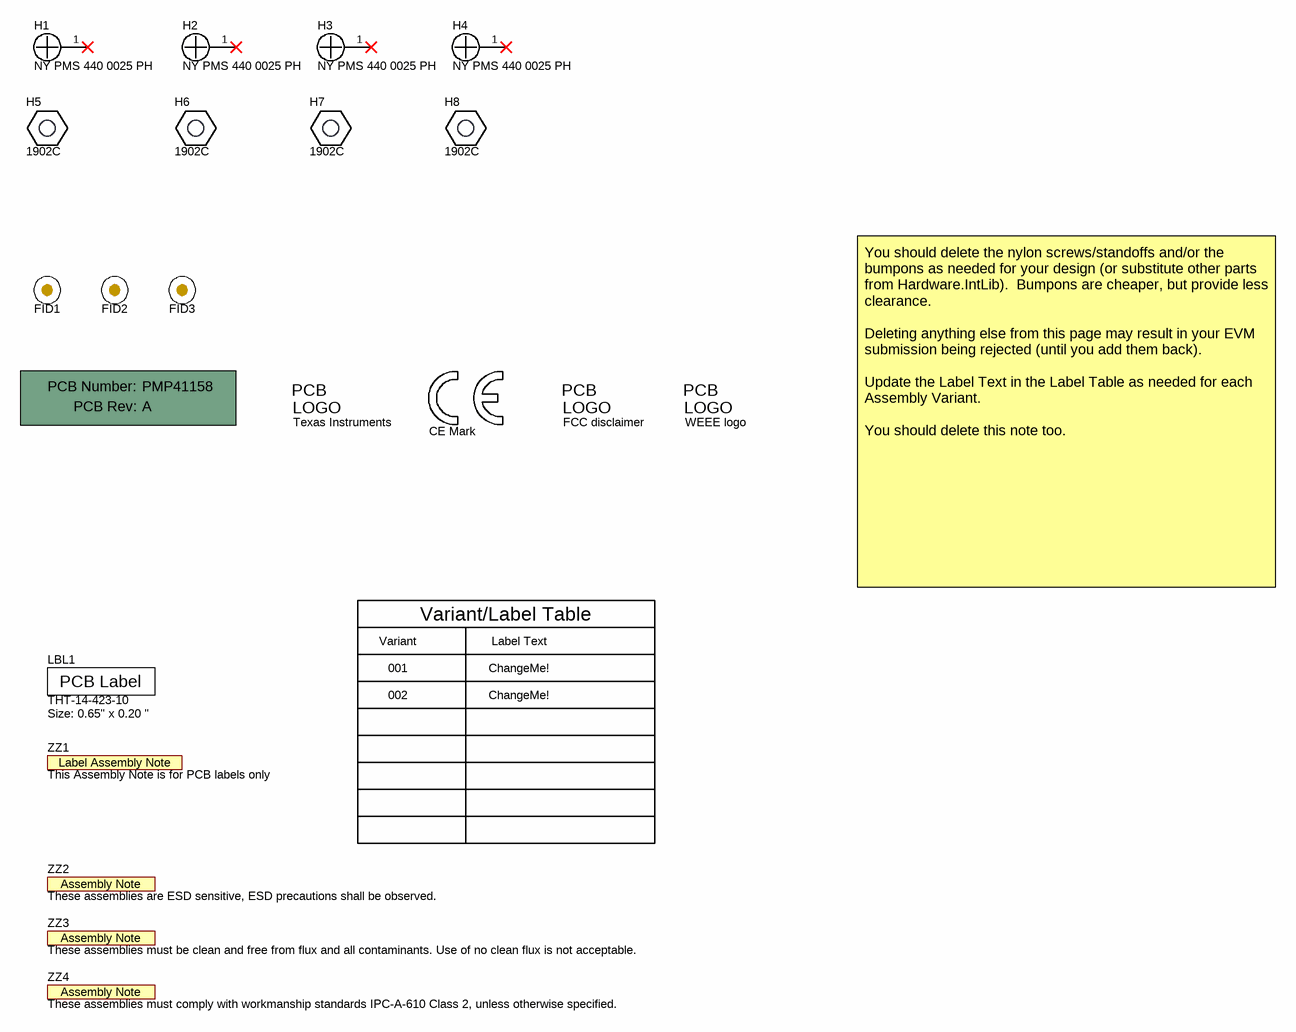
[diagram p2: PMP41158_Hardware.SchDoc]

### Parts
!PCB1  Printed Circuit Board  (value not drawn)  (mechanical)
FID1  Fiducial  [Fiducial10-20]  (value not drawn)
FID2  Fiducial  [Fiducial10-20]  (value not drawn)
FID3  Fiducial  [Fiducial10-20]  (value not drawn)
H1  NY PMS 440 0025 PH  [NY PMS 440 0025 PH]
H2  NY PMS 440 0025 PH  [NY PMS 440 0025 PH]
H3  NY PMS 440 0025 PH  [NY PMS 440 0025 PH]
H4  NY PMS 440 0025 PH  [NY PMS 440 0025 PH]
H5  1902C  [Keystone_1902C]
H6  1902C  [Keystone_1902C]
H7  1902C  [Keystone_1902C]
H8  1902C  [Keystone_1902C]
LBL1  THT-14-423-10  Note: Size: 0.65" x 0.20 "  [Label_650x200]
Logo1  CE Mark  [CE_Mark_5mm]  (no BOM)
Logo2  Texas Instruments  [TI_Stacked_Overlay_Small]  (no BOM)
Logo3  FCC disclaimer  [FCC_disclaimer]  (no BOM)
Logo4  WEEE logo  [WEEE_Minimum]  (no BOM)
ZZ1  This Assembly Note is for PCB labels only  [AssemblyNoteLabel]  (no BOM)
ZZ2  These assemblies are ESD sensitive, ESD precautions shall be observed.  [AssemblyNote]  (no BOM)
ZZ3  These assemblies must be clean and free from flux and all contaminants. Use of no clean flux is not acceptable.  [AssemblyNote]  (no BOM)
ZZ4  These assemblies must comply with workmanship standards IPC-A-610 Class 2, unless otherwise specified.  [AssemblyNote]  (no BOM)

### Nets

Not connected (* = marked no-connect by the designer): H1 1*; H2 1*; H3 1*; H4 1*

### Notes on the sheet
- Variant
- Variant/Label Table
- Label Text
- You should delete the nylon screws/standoffs and/or the bumpons as needed for your design (or substitute other parts from Hardware.IntLib).  Bumpons are cheaper, but provide less clearance.
  Deleting anything else from this page may result in your EVM submission being rejected (until you add them back).
  Update the Label Text in the Label Table as needed for each Assembly Variant.
  You should delete this note too.
- 001
- 002
- ChangeMe!

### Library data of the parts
!PCB1 = CMP-0003618-2: Manufacturer: Any; PartNumber: PMP41158
FID1-FID3 = CMP-0077181-1: Fiducial mark.  There is nothing to buy or mount.
H1-H4 = CMP-0003617-1: Machine Screw, Round, #4-40 x 1/4, Nylon, Philips panhead; Manufacturer: B&F Fastener Supply; CompType: Hardware
H5-H8 = CMP-0003610-1: Standoff, Hex, 0.5"L #4-40 Nylon; Manufacturer: Keystone; CompType: Hardware
LBL1 = CMP-0003625-1: Thermal Transfer Printable Labels, 0.650" W x 0.200" H - 10,000 per roll; Manufacturer: Brady; CompType: Label
Logo1 = CMP-0074844-1: SymbolCreator: a0412235
Logo2 = CMP-0074838-1: Texas Instrument Corporate Signature; SymbolCreator: a0412235; Lib Reference: TI_Logo; Library Reference: Logo
Logo3 = CMP-0074847-1: FCC_disclaimer; Library Reference: Logo
Logo4 = CMP-0074769-1
ZZ1 = CMP-0003616-3
ZZ2 = CMP-0077236-1
ZZ3 = CMP-0077237-1
ZZ4 = CMP-0077238-1

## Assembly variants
EMI-01: not fitted C104 C105 C106 C107 FID1 FID2 FID3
